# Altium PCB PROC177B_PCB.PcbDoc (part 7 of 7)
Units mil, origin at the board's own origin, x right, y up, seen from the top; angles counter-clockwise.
Board outline 4257.98 x 1561.15 mil, 4 copper layers (Top Layer, Int1 (GND), Int2 (PWR), Bottom Layer), stack 63.572 mil thick; 461 components, 307 nets, 1564 pads, 607 vias.
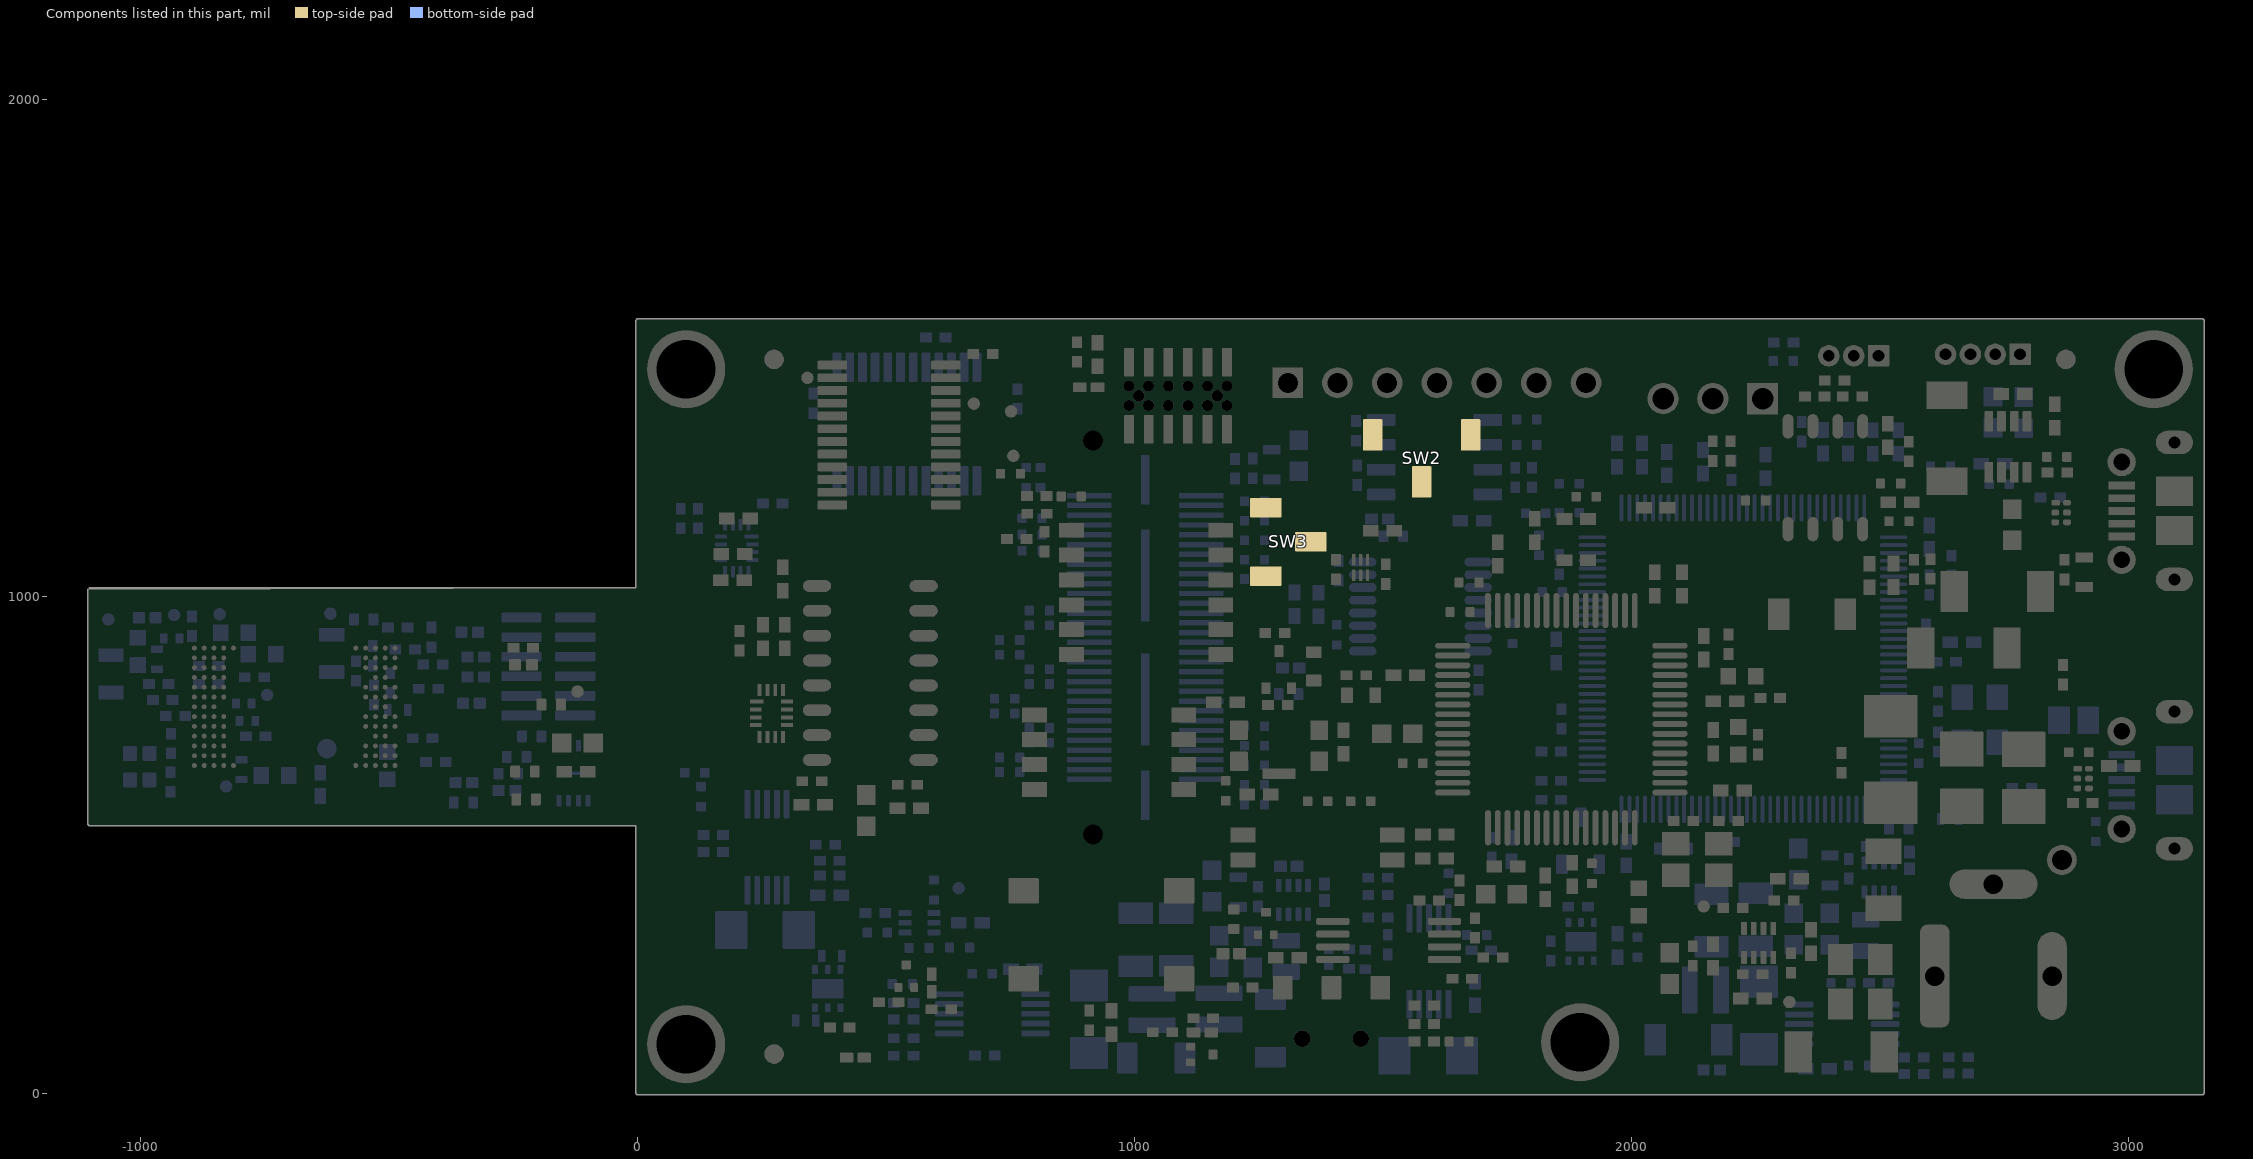
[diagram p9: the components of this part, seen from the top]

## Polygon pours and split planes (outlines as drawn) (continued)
VCC_SNSR_BRD on Bottom Layer "NONET_L08_P-001" (solid, remove dead copper, pour order 273): 1040,1542 980,1542 977,1539 977,1517 987,1507 1032,1507 1040,1515
VCC_SNSR_BRD on Bottom Layer "NONET_L08_P-001" (solid, remove dead copper, pour order 272): 1628.18,1272 1600,1272 1591,1263 1591,1233 1600,1224 1616,1224 1628.18,1236.18
VCC_3V3 on Bottom Layer "NONET_L08_P-001" (solid, remove dead copper, pour order 264): 17 vertices, not listed, extent 1636.25,1139.72 1780.1,1230.79
5V_IN on Bottom Layer "NONET_L08_P-001" (solid, remove dead copper, pour order 177): 18 vertices, not listed, extent 1111.91,403.48 1316.27,485.41
RADAR_1V8 on Bottom Layer "NONET_L08_P-001" (solid, remove dead copper, pour order 2): 25 vertices, not listed, extent -905.85,787.63 -810.81,976.73
RADAR_3V3 on Bottom Layer "NONET_L08_P-001" (solid, remove dead copper, pour order 26): 42 vertices, not listed, extent -477.29,613.27 -274.01,939.31
RADAR_1V8 on Bottom Layer "NONET_L08_P-001" (solid, remove dead copper, pour order 94): 27 vertices, not listed, extent -458.71,852.89 -404.39,907.91
5V_IN on Bottom Layer "NONET_L08_P-001" (solid, remove dead copper, pour order 161): 31 vertices, not listed, extent 2049,299.42 2494.08,518.33
REG_OUT_1V8 on Bottom Layer "NONET_L08_P-001" (solid, remove dead copper, pour order 171): 17 vertices, not listed, extent 2088.1,157.66 2528.67,330.96
RADAR_1V8 on Bottom Layer "NONET_L08_P-001" (solid, remove dead copper, pour order 174): 2295.93,123.74 2219.15,123.74 2217.51,122.55 2217.51,36.2 2225.44,28.27 2266.42,28.27 2295.93,57.79
VCC_3V3 on Bottom Layer "NONET_L08_P-001" (solid, remove dead copper, pour order 185): 837.7,193.38 842.24,197.92 842.24,250.87 831.61,261.5 783.66,261.5 783.66,226.96 772.06,215.36 772.06,194.95 773.63,193.38
5V_IN on Bottom Layer "NONET_L08_P-001" (solid, remove dead copper, pour order 198): 2760.39,1506.29 2760.39,1447.21 2770.37,1437.24 2770.37,1371.01 2807.77,1371.01 2807.77,1410.38 2803.7,1414.45 2803.7,1506.29 2801.75,1508.24 2762.34,1508.24
GND on Bottom Layer "NONET_L08_P-001" (solid, remove dead copper, pour order 226): 40 vertices, not listed, extent 2126.02,343.05 2569.34,460.64
VCC_XDS_3V3 on Bottom Layer "NONET_L-01_P-001" (solid, remove dead copper, pour order 247): 25 vertices, not listed, extent 1783.24,713.01 1952.19,884.16
VCC_XDS_3V3 on Bottom Layer "NONET_L-01_P-001" (solid, remove dead copper, pour order 248): 38 vertices, not listed, extent 2053.49,1089.14 2321.7,1288.64
VCC_XDS_3V3 on Bottom Layer "NONET_L-01_P-001" (solid, remove dead copper, pour order 249): 46 vertices, not listed, extent 2436.7,717.68 2753,1060.14
CONN_5V on Bottom Layer "NONET_L08_P-001" (solid, remove dead copper, pour order 202): 18 vertices, not listed, extent 1090,1177.06 1379,1271.99
5V_IN on Bottom Layer "NONET_L08_P-001" (solid, remove dead copper, pour order 206): 1311.95,1339.21 1320.7,1347.96 1365.57,1347.96 1375.12,1338.41 1375.12,1302.59 1366.82,1294.29 1311.95,1294.29
RADAR_3V3 on Bottom Layer "NONET_L08_P-001" (solid, remove dead copper, pour order 192): 45 vertices, not listed, extent -257.13,259.33 222.37,637.61
RADAR_1V2 on Bottom Layer "NONET_L08_P-001" (solid, remove dead copper, pour order 57): 46 vertices, not listed, extent -639.7,806 120.73,999.8
RADAR_1P2_RF on Bottom Layer "  " (solid, remove dead copper, pour order 95): 27 vertices, not listed, extent -1088.05,813.27 -899.7,966.28
RADAR_1V_RF_OUT on Bottom Layer "NONET_L08_P-001" (solid, remove dead copper, pour order 8): -801.35,698.05 -780.94,677.64 -780.94,660.92 -804.64,660.92 -804.64,672.1 -809.73,677.19 -823.04,677.19 -827.91,682.06 -827.91,692.49 -822.34,698.05
SW3 on Bottom Layer "NONET_L08_P-001" (solid, remove dead copper, pour order 221): 19 vertices, not listed, extent 2434.97,333.78 2499.53,417.95
SW2 on Bottom Layer "NONET_L08_P-001" (solid, remove dead copper, pour order 180): 22 vertices, not listed, extent 1277.92,291.2 1333.17,373.76
GND on Bottom Layer "NONET_L08_P-001" (solid, remove dead copper, pour order 179): 27 vertices, not listed, extent 958.8,296.38 1392.83,404.94
REG_OUT_1V2 on Bottom Layer "NONET_L08_P-001" (solid, remove dead copper, pour order 181): 19 vertices, not listed, extent 970.29,184.22 1443.41,277.5
VCC_XDS_3V3 on Bottom Layer "NONET_L-01_P-001" (solid, remove dead copper, pour order 262): 21 vertices, not listed, extent 1821.14,1017.45 1950.43,1061.5
RADAR_1P2_RF on Bottom Layer "NONET_L08_P-001" (solid, remove dead copper, pour order 188): 1622.85,113.52 1622.85,43.46 1622.37,42.99 1627.83,37.53 1700.51,37.53 1738.48,75.5 1738.48,118.06 1727.22,129.32 1698.48,129.32 1682.68,113.52
REG_1V2 on Bottom Layer "NONET_L08_P-001" (solid, remove dead copper, pour order 182): 867.12,50.25 895.95,21.41 940.64,21.41 1014.16,21.19 1014.16,99.91 1032.91,118.66 1082.64,118.66 1086.01,122.03 1086.01,148.02 1081.31,152.72 963.04,152.72 941.95,131.64 868.13,131.64 867.73,132.04 867.12,131.43
RADAR_3V3 on Bottom Layer "NONET_L08_P-001" (solid, remove dead copper, pour order 105): -439.41,724.22 -505.88,724.22 -522.98,707.12 -522.98,676.26 -517.63,670.91 -486.76,670.91 -475.58,682.09 -467.56,682.09 -463.18,686.46 -463.18,698.13 -457.59,703.72 -439.61,703.72
VCC_LVDS_3V3 on Bottom Layer "NONET_L08_P-001" (solid, remove dead copper, pour order 213): 599.76,682.34 606.38,675.72 609,673.1 609,651.6 591.91,634.52 508.28,634.52 502.84,639.96 502.84,677.38 507.8,682.34
CONN_5V on Bottom Layer "NONET_L08_P-001" (solid, remove dead copper, pour order 203): 964.1,1196.74 970.12,1190.72 998.95,1190.72 1004.5,1195.93 1004.5,1227.53 998.21,1233.82 875.22,1233.82 865,1223.6 864.73,1196.74
GND on Bottom Layer "NONET_L08_P-001" (solid, remove dead copper, pour order 195): 21 vertices, not listed, extent 1827.85,285.23 1983.74,389.4
5V_IN on Bottom Layer "NONET_L08_P-001" (solid, remove dead copper, pour order 194): 1814,299.58 1811.37,302.21 1791.7,302.21 1786,296.51 1786,286.8 1786,258.86 1793.76,251.1 1870.6,251.1 1877.17,257.67 1878.24,257.67 1879.12,258.55 1879.12,274.25 1875.19,278.17 1824.38,278.17 1814,288.56
5V_IN on Bottom Layer "NONET_L08_P-001" (solid, remove dead copper, pour order 208): 20 vertices, not listed, extent 350.69,119.48 476.15,197.6
GND on Bottom Layer "NONET_L08_P-001" (solid, remove dead copper, pour order 193): 23 vertices, not listed, extent 295.67,113.54 448,291.6
VCC_3V3 on Bottom Layer "NONET_L08_P-001" (solid, remove dead copper, pour order 190): 22 vertices, not listed, extent 292.86,240.03 386.07,437.12
REG_RF_1V2 on Bottom Layer "NONET_L08_P-001" (solid, remove dead copper, pour order 183): 20 vertices, not listed, extent 1123.18,21.97 1558.27,154.1
GND on Bottom Layer "NONET_L08_P-001" (solid, remove dead copper, pour order 187): 1242.5,208.84 1242.5,168.94 1267.2,144.24 1341.83,144.24 1357.16,159.57 1357.16,193.44 1341.26,209.34 1243.01,209.34
GND on Bottom Layer "NONET_L08_P-001" (solid, remove dead copper, pour order 204): 1192.93,1264.23 1247.87,1264.23 1268.16,1284.52 1294.27,1284.52 1294.27,1311.87 1273.38,1332.76 1215.43,1332.76 1192.98,1310.32
RADAR_SRAM_1V2 on Bottom Layer "NONET_L08_P-001" (solid, remove dead copper, pour order 56): -541.41,962.33 -539.43,964.31 -489.05,964.31 -482.85,958.07 -482.85,903.61 -481.88,902.64 -473.42,902.64 -473.42,882.66 -481.86,874.22 -509.12,874.22 -513.89,878.99 -513.89,938.88 -517.26,942.25 -538.69,942.25 -541.41,944.98
VBUS_1_DETECT on Bottom Layer "NONET_L08_P-001" (solid, remove dead copper, pour order 207): 1944.87,634.29 1882.52,634.29 1874.43,642.38 1850.81,642.38 1846.87,638.44 1846.87,580.76 1870.49,580.76 1870.49,600.44 1884.65,614.6 1942.5,614.6 1948.81,620.91 1948.81,632.49 1947,634.3
LIN_VDD on Bottom Layer "NONET_L08_P-001" (solid, remove dead copper, pour order 201): 2679.48,1349.09 2679.48,1331.72 2693.18,1318.02 2807.77,1318.02 2807.77,1358.15 2688.54,1358.15
VBAT on Bottom Layer "NONET_L08_P-001" (solid, remove dead copper, pour order 200): 2708.68,1500.68 2708.68,1475.28 2717.81,1466.15 2717.81,1420.05 2708.89,1411.14 2708.89,1371.77 2746.3,1371.77 2746.3,1470.11 2754.18,1477.99 2754.18,1498.01 2742.05,1510.14 2724.86,1510.14
VCC_3V3 on Bottom Layer "NONET_L08_P-001" (solid, remove dead copper, pour order 189): 1714.77,196.84 1727,184.6 1727,165.6 1712.79,151.4 1626.91,151.4 1625.53,151.97 1624.96,152.54 1624.96,207.34 1626.11,208.48 1635.63,208.48 1636.77,207.34 1636.77,206.53 1646.47,196.84
GND on Bottom Layer "NONET_L08_P-001" (solid, remove dead copper, pour order 186): 1139.65,106.27 1149.17,96.76 1149.17,47.52 1137.06,35.41 1057.69,35.41 1052.57,40.52 1052.57,98.69 1060.16,106.27
RADAR_1V2 on Bottom Layer "NONET_L08_P-001" (solid, remove dead copper, pour order 184): 862.29,272.12 862.29,288.89 874,300.6 935,300.6 949.02,286.58 949.02,165.6 868.04,165.6 861.61,172.04 861.7,172.13 861.7,271.53
GND on Bottom Layer "NONET_L08_P-001" (solid, remove dead copper, pour order 176): 2026.14,138.95 2098.65,138.95 2104,133.6 2104,81.84 2092.21,70.05 2032.04,70.05 2026.14,75.96
VCC_3V3 on Bottom Layer "NONET_L08_P-001" (solid, remove dead copper, pour order 175): 2308.75,57.07 2291.19,39.51 2283.17,31.49 2283.17,20.8 2289.09,14.88 2289.28,15.07 2312.92,15.07 2356.49,15.07 2371,29.59 2371,101.17 2371.31,101.48 2367.2,105.58 2310.95,105.58 2308.75,103.37
REG_1V8 on Bottom Layer "NONET_L08_P-001" (solid, remove dead copper, pour order 173): 2296.86,182.15 2235.1,182.15 2203.96,151.01 2203.96,78.23 2196.99,71.26 2160.21,71.26 2152.65,78.82 2152.65,148.17 2164.38,159.91 2164.38,252.78 2173.45,261.85 2289.61,261.85 2296.86,254.59
GND on Bottom Layer "NONET_L08_P-001" (solid, remove dead copper, pour order 103): -528.45,936.11 -522.06,929.72 -522.06,888.13 -541.74,888.13 -551.64,898.03 -556.38,898.03 -574.56,916.21 -574.56,928.42 -566.87,936.11
GND on Bottom Layer "NONET_L08_P-001" (solid, remove dead copper, pour order 25): -84.38,713.31 -78.02,706.94 -78.02,655.09 -93.13,639.98 -158.49,639.98 -159.66,641.14 -159.66,650.66 -156.03,654.29 -119.32,654.29 -104.12,669.48 -104.12,710.55 -101.36,713.31
RADAR_1V_RF_OUT on Bottom Layer "NONET_L08_P-001" (solid, remove dead copper, pour order 107): 19 vertices, not listed, extent -823.54,826.28 -766.31,901.26
RADAR_1V4_APLL on Bottom Layer "NONET_L08_P-001" (solid, remove dead copper, pour order 11): -796.96,774.77 -804.54,767.19 -823.82,767.19 -827.95,762.89 -838.81,762.89 -841.42,765.5 -841.42,774.91 -831.38,784.95 -826.83,784.95 -813.98,797.8 -800.21,797.8 -796.96,794.55
RADAR_3V3 on Bottom Layer "NONET_L08_P-001" (solid, remove dead copper, pour order 42): -265.85,775.7 -271.26,770.28 -278.8,770.28 -278.8,722.93 -259.72,703.85 -219.2,703.85 -215.2,707.85 -215.2,730.47 -200.83,744.84 -187.4,744.84 -184.1,748.14 -184.57,748.61 -184.57,771.46 -188.11,774.99
RADAR_1V4_SYNTH on Bottom Layer "NONET_L08_P-001" (solid, remove dead copper, pour order 12): -792.57,758.77 -822.37,758.77 -827.03,754.1 -827.03,742.69 -822.71,738.37 -792.29,738.37 -790.2,740.46 -790.2,755.71
RADAR_1V8 on Bottom Layer "NONET_L08_P-001" (solid, remove dead copper, pour order 7): -922.93,771.24 -873.18,771.24 -871.82,769.88 -868.73,766.79 -868.73,750.61 -875.34,744 -920.63,744 -924.99,748.36 -924.99,769.18
RADAR_VBGAP on Bottom Layer "NONET_L08_P-001" (solid, remove dead copper, pour order 6): -891.37,799.43 -891.37,784.57 -894.97,780.97 -946.15,780.97 -946.66,781.48 -946.66,800.98 -945.96,801.68 -893.62,801.68
GND on Int2 (PWR) "NONET_L08_P-001" (solid, remove dead copper, pour order 261): 12.56,1542.25 3136.17,1542.25 3136.17,12.61 12.56,12.61
GND on Int2 (PWR) "NONET_L08_P-001" (solid, remove dead copper, pour order 212): -1089.6,1001.51 0.02,1001.51 0.02,541.26 -1089.6,541.26
RADAR_1P2_RF on Int2 (PWR) "RADAR_1P2_RF_L03_P148" (solid, remove dead copper, pour order 148): 49 vertices, not listed, extent -1089.13,52.72 1739.1,1001.09
GND on Int2 (PWR) "NONET_L08_P-001" (solid, remove dead copper, pour order 216): 802.38,1028.27 757.04,1073.6 308.73,1073.6 308.73,629.5 411.2,527.03 753.43,527.03 802.38,575.98
5V_IN on Int2 (PWR) "NONET_L08_P-001" (solid, remove dead copper, pour order 232): 39 vertices, not listed, extent 439.76,156.18 2118.02,481.06
RADAR_1V8 on Int2 (PWR) "NONET_L08_P-001" (solid, remove dead copper, pour order 209): 18 vertices, not listed, extent -890.33,871.64 127.75,996.77
RADAR_1V8 on Int2 (PWR) "Int2 (PWR)-RADAR_1V8" (solid, remove dead copper, pour order 205): 44 vertices, not listed, extent 70.42,4.64 2288,390.02
RADAR_1V2 on Int2 (PWR) "NONET_L-01_P-001" (solid, remove dead copper, pour order 152): 17 vertices, not listed, extent 138.86,255.71 926.72,632.03
RADAR_1V8 on Int2 (PWR) "NONET_L08_P-001" (solid, remove dead copper, pour order 246): 106.3,923 98.54,915.24 98.54,883.89 98.42,883.77 105.42,876.77 117.42,876.77 125.42,884.77 125.42,916.77 119.42,922.77
GND on Int1 (GND) "Int1 (GND)-GND" (solid, remove dead copper, pour order 265): 12.42,13.72 3136.49,13.72 3136.49,1542.71 12.42,1542.71 12.42,1006.87 -1094.56,1006.87 -1094.56,553.75 12.42,553.75

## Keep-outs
Top Layer:
  region: -472.42,541.26 -472.42,1013.78 -275.57,1013.78 -275.57,541.26
  region: -905.49,1013.78 -905.49,541.26 -1102.34,541.26 -1102.34,1013.78
Keep-Out Layer:
  circle w4: c3051.18,1456.69 r118.11
  circle w4: c1896.85,102.75 r118.11
  circle w1: c917.09,1313.06 r30
  circle w1: c917.09,520.54 r30
  circle w6: c98.41,1456.71 r118.11
  circle w6: c98.43,98.43 r118.11
  text ".Layer_Name" at -304.89,-905.63 h60

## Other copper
Top Layer:
  text ".Layer_Name" at -554.89,-905.63 h60
Int1 (GND):
  text ".Layer_Name" at -537,-906 h60
Int2 (PWR):
  text ".Layer_Name" at -537,-906 h60
Bottom Layer:
  pour cut-out: -964.32,745.39 -894.72,745.39 -870.69,721.35 -870.69,616.21 -905.29,581.6 -1047.34,581.6 -1066.93,601.2 -1066.93,707.17 -1041.55,732.56 -976.54,732.56
  text ".Layer_Name" at -554.89,-905.63 h60

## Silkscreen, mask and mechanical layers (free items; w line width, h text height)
Top Overlay:
  drawing of 205 lines, arcs and shapes, not listed
  text "GND" at 1166.86,1512.5 h25
  text "3V3" at 957,1512 h25
  text "HOST_CLK" at 447.09,1498.93 h25
  text "CAN" at 2579.27,1478.04 h23 r90
  text "LIN" at 2661.08,1440.84 h20
  text "NERROR" at 803.39,1374.87 h22
  text "WU_REQIN" at 198.41,1367.83 h20
  text "SPI_HEADER" at 1256.42,1364.95 h25
  text "RTC_CLK" at 699.28,1336.88 h23
  text "SDA" at 2113.42,1335.47 h25
  text "SCL" at 2225.05,1332.57 h25
  text "GND" at 2023.47,1329.12 h25
  text "5V" at 1356.52,1312.91 h25
  text "3V3" at 1753.89,1308.42 h25
  text "P_CLKO" at 742.62,1298.13 h22
  text "I2C" at 2025.24,1280.35 h25
  text "I/F CONN" at 1106.5,1263.9 h25
  text "SOP1" at 1101.69,1207 h26
  text "JTAG" at 685.26,1055.05 h26
  text "LVDS" at 732.77,1015.03 h26
  text "XDS_USB" at 2973.88,972 h22
  text "TEXAS" at -404.33,967.76 h20
  text "RS232" at 711.33,967.76 h26
  text "INSTRUMENTS" at -458.14,928.97 h20
  text "FOR DEMO" at 2898.69,924.89 h30
  text "CAN/UARTA" at 615.09,920.17 h26
  text "PGOOD" at 1402.3,906.14 h24
  text "I2C/SPI" at 675.76,870.48 h26
  text "FTDI" at 1521.52,789.29 h20
  text "SOP1" at -134.37,765.65 h25
  text "USER_SW" at 1340.35,763.77 h20
  text "CAN_EN" at 623.4,754.63 h25
  text "LIN_EN" at 627.41,707.14 h25
  text "FTDI_DCA" at 609.79,663.15 h21
  text "_SPI" at 643.97,628.96 h21
  text "R" at -918.61,627.51 h4.54
  text "R" at -918.61,627.51 h4.54
  text "PROC177 REV. B" at 166,613 h40 r90
  text "PROC177 REV. B" at -819.21,576.62 h40
  text "MISTRAL" at -1073.25,562.27 h41.62
  text "R" at 802.67,525.72 h4.54
  text "R" at 802.67,525.72 h4.54
  text "XDS_I2C_SW" at 993.66,496.14 h20
  text "GND" at 2755.89,470.97 h25
  text "MISTRAL" at 648.03,460.47 h41.62
  text "SL#" at 83.19,305.04 h40
  text "RESET_SW" at 703.13,124.62 h25
  text "U_LED" at 1240.28,87.52 h20 r90
  text "5V" at 361.92,63.1 h20
  text "RESET_LED" at 689.15,56.7 h25 r90
  text "5V_PWR" at 3004.44,25.27 h22
  text "FUNCTIONAL MODE" at 892.47,23.88 h23
  text "FLASHING MODE" at 1546.83,11.32 h23
  text ".Layer_Name" at -304.89,-905.63 h60
Bottom Overlay:
  circle w15: c1445.29,1191.56 r2.66
  circle w15: c1350.5,156.17 r3.1
  circle w15: c1739.06,1076.55 r3.1
  circle w15: c1850.21,363.54 r0.51
  lines w4: -919.68,961.79 -919.68,967.22 -914.3,972.6 ; 474.1,183.6 480.54,177.17 497.41,177.17 ; 711.93,842.64 720.2,834.38 772.25,834.38 ; 726,963.6 730.78,958.82 737.76,958.82 772.37,958.82 ; 776,929.6 776,979.6 ; 776.21,815.6 776.3,815.52 776.3,851.99 ; 816.01,674.15 816.01,634.88 827,623.89 ; 944,25.6 956,37.6 956,38.6 956,124.13 970.48,138.61 970.48,159.13 ; 1055,428.6 1105.51,428.6 1122.77,411.34 1122.77,376.43 1122.77,351.64 1123.37,351.05 1123.37,350.63 1128.94,345.05 1198.01,345.05 1198.51,344.55 ; 2240,492.6 2240,515.96 2260.84,536.8 2419.3,536.8 2435.27,520.83 2435.27,487.65 ; 2418.87,253.22 2455.49,253.22 2459,249.72 ; 2578,649.6 2578,639.58 2588.97,628.6
  text "VBAT" at 2766.41,1514.38 h20
  text "GND" at 2473.1,1509.24 h23
  text "CANL" at 2526.75,1462.26 h23 r270
  text "CANH" at 2348.88,1455.52 h23 r270
  text "I2C_HEADER" at 2209.65,1447.1 h25
  text "5V_IN" at 2827.4,1438.49 h20
  text "GND" at 2618.55,1391.51 h23 r270
  text "DCA1000_CONN" at 1168.87,1348.49 h25
  text "LIN_BUS" at 2661.77,1307.91 h23 r270
  text "I/F CONN" at -104.24,981.36 h20
  text "GPADC1" at -844.4,978.54 h20
  text "1V2" at -622.29,978.09 h20
  text "GND" at -278.75,965.26 h20
  text "1V8" at -770.19,951.07 h20
  text "1P2RF" at -1047.71,898.98 h20 r270
  text "TEXAS" at 2935.21,891.52 h25
  text "INSTRUMENTS" at 2996.07,856.02 h25
  text "GND" at -752.15,732.38 h20 r270
  text "3V3" at -260.49,722.9 h20
  text "VPP" at -642.78,716.8 h25 r270
  text "FY23-24/01286000102" at 276.04,645.94 h25 r270
  text "OSC_CLKOUT" at -713.26,571.59 h22
  text "3V3" at 731.41,434.71 h25
  text "FTDI_USB" at 3115.28,423.93 h25
  text "FOR RAW ADC" at 3120.15,373.06 h25
  text ".Layer_Name" at -304.89,-905.63 h60
Top Paste:
  region: -781.45,721.97 -719.54,721.97 -719.54,672.03 -781.45,672.03
  region: -712.73,721.97 -650.82,721.97 -650.82,672.03 -712.73,672.03
  region: -712.73,897.71 -650.82,897.71 -650.82,847.78 -712.73,847.78
  region: -712.73,839.31 -650.82,839.31 -650.82,789.38 -712.73,789.38
  region: -712.73,780.55 -650.82,780.55 -650.82,730.62 -712.73,730.62
  region: -781.45,780.55 -719.54,780.55 -719.54,730.62 -781.45,730.62
  region: -781.45,839.31 -719.54,839.31 -719.54,789.38 -781.45,789.38
  region: -781.45,897.71 -719.54,897.71 -719.54,847.78 -781.45,847.78
  text ".Layer_Name" at -304.89,-905.63 h60
Bottom Paste:
  text ".Layer_Name" at -304.89,-905.63 h60
Top Solder:
  region: -712.73,897.71 -650.82,897.71 -650.82,847.78 -712.73,847.78
  region: -712.73,839.31 -650.82,839.31 -650.82,789.38 -712.73,789.38
  region: -712.73,780.55 -650.82,780.55 -650.82,730.62 -712.73,730.62
  region: -712.73,721.97 -650.82,721.97 -650.82,672.03 -712.73,672.03
  region: -781.45,721.97 -719.54,721.97 -719.54,672.03 -781.45,672.03
  region: -781.45,780.55 -719.54,780.55 -719.54,730.62 -781.45,730.62
  region: -781.45,839.31 -719.54,839.31 -719.54,789.38 -781.45,789.38
  region: -781.45,897.71 -719.54,897.71 -719.54,847.78 -781.45,847.78
  text ".Layer_Name" at -304.89,-905.63 h60
  text ".Layer_Name" at -304.89,-905.63 h60
Bottom Solder:
  region: -724.57,857.15 -651.21,857.15 -651.21,696.47 -724.57,696.47
  lines w20: -1090.48,553.27 -1009.45,553.27 ; -1090.34,555.79 -1090.34,601.79 ; -1090.35,703.54 -1090.35,753.54 ; -1089.36,980.6 -1089.36,1002.6 -1029.36,1002.61 ; -906.45,553.27 -756.45,553.27 ; -656.45,553.27 -506.45,553.27 ; -56.95,659.44 -56.95,689.44
  text ".Layer_Name" at -304.89,-905.63 h60
Drill Guide:
  text ".Layer_Name" at -304.89,-905.63 h60
M1 Board Outline:
  lines w6: -1102.34,541.26 0.02,541.26 ; -1102.34,541.34 -1102.34,1013.78 0.02,1013.78 ; -1102.34,560.94 -1102.34,994.1 ; -1082.65,541.26 0.02,541.26 ; -1082.65,1013.78 0.02,1013.78 ; 222.1,0 0,0 ; 222.12,1555.12 0,1555.12 ; 371.71,0 2847.22,0 ; 371.73,1555.12 2847.2,1555.12 ; 2996.82,0 3149.61,0 ; 0,0 0.02,541.26 ; 0,0 3149.61,0 ; 0,0 0.02,541.26 ; 0.02,1013.78 0.01,1555.12 ; 0.02,1013.78 0,1555.12 ; 0,1555.12 0.02,1555.12 ; 0,1555.12 3149.61,1555.12 ; 3149.61,0 3149.61,1555.12 ; 3149.61,0 3149.61,1555.12 ; 3149.61,1555.12 3149.61,1555.12 ; -36.37,625.39 ccw(c-11.37,625.39) -11.37,600.39 11.4,600.39 ccw(c11.4,625.39) 36.4,625.39 36.4,650.05 ccw(c11.4,650.05) 11.4,675.05 -11.36,675.05 ccw(c-11.37,650.05) -36.37,650.05 -36.37,625.39 ; -36.36,905.07 ccw(c-11.36,905.07) -11.36,880.07 11.4,880.07 ccw(c11.4,905.07) 36.4,905.07 36.4,929.72 ccw(c11.4,929.72) 11.4,954.72 -11.36,954.72 ccw(c-11.36,929.72) -36.36,929.72 -36.36,905.07 ; -36.36,914.98 -36.36,914.98 ; -36.36,620.42 -34.93,615.69 -32.58,611.27 -29.41,607.39 -25.55,604.21 -21.13,601.85 -16.34,600.39 -12.02,600.37 9.49,599.68 11.16,599.64 16.2,600.18 21.03,601.68 25.49,604.09 29.39,607.31 32.6,611.23 36.4,620.42 36.41,655.02 34.98,659.74 32.63,664.17 29.46,668.04 25.59,671.23 21.17,673.59 16.38,675.05 -16.34,675.05 -21.06,673.62 -25.49,671.26 -29.37,668.08 -32.56,664.21 -36.36,655.02 -36.36,620.42 ; -36.36,760.26 -34.93,755.54 -32.58,751.11 -29.41,747.23 -25.54,744.05 -21.12,741.69 -16.33,740.23 -13.98,740.23 13.62,740.81 16.6,741.11 21.31,742.38 25.66,744.57 29.5,747.59 32.64,751.31 34.98,755.6 36.41,760.26 36.41,794.86 34.98,799.6 32.62,804.02 29.45,807.89 25.59,811.07 21.17,813.43 16.38,814.88 -16.33,814.88 -21.07,813.45 -25.49,811.1 -29.36,807.93 -32.54,804.06 -34.91,799.65 -36.36,794.86 -36.36,760.26 ; -36.36,765.23 ccw(c-11.36,765.23) -11.36,740.23 11.41,740.23 ccw(c11.41,765.23) 36.41,765.23 36.41,789.89 ccw(c11.41,789.89) 11.41,814.89 -11.36,814.89 ccw(c-11.36,789.89) -36.36,789.89 -36.36,765.23 ; -36.36,900.1 -36.36,934.69 -34.91,939.48 -32.54,943.9 -29.36,947.76 -25.49,950.94 -21.07,953.29 -16.33,954.72 16.38,954.72 25.57,950.92 29.44,947.73 32.62,943.85 34.97,939.43 36.41,934.69 36.41,900.1 34.96,895.31 32.59,890.89 29.41,887.03 25.54,883.85 21.12,881.5 16.38,880.07 -16.33,880.07 -25.52,883.87 -29.39,887.06 -32.57,890.94 -34.92,895.36 -36.36,900.1
M2 Board Dimensions:
  text ".Layer_Name" at -566.77,-903.68 h60
M3 3D STEP Top:
  text ".Layer_Name" at -304.89,-905.63 h60
M4 3D STEP Bottom:
  text ".Layer_Name" at -304.89,-905.63 h60
M5 Assembly Top:
  lines w1: 1662.26,555.72 1662.26,555.87
  lines w2.67: 69.62,433.23 ccw(c82.97,433.23) 82.97,419.88 403.47,419.88 ccw(c403.47,433.23) 416.83,433.23 416.83,513.36 ccw(c403.47,513.36) 403.47,526.71 82.97,526.71 ccw(c82.97,513.36) 69.62,513.36 69.62,433.23
  lines w10: -1173.89,-977.3 5426.11,-977.3 ; -1173.89,-773.97 5428.11,-773.97 ; -1173.89,-570.63 -1173.89,-1180.63 2831.11,-1180.63 5428.11,-1180.63 5428.11,-570.63 -1173.39,-570.63 -1173.39,-1180.63 402.11,-1180.63 ; 1291.11,-1180.63 1291.11,-570.63 ; 2558.11,-773.97 2558.11,-570.63 ; 3398.11,-773.97 3398.11,-570.63 ; 4020.11,-1187.13 4020.11,-984.3
  text "COMPONENTS MARKED 'DNP' SHOULD NOT BE POPULATED." at -95.68,3736.39 h60
  text "ASSEMBLY VARIANT:" at -96.18,3620.89 h60
  text ".VariantName" at 939.82,3620.89 h60
  text ".Designator" at 211.17,462.61 h21.37
  text "PCB VIEWED FROM TOP SIDE" at -1099.62,-700.81 h60
  text "BOARD #:" at 1376.88,-700.81 h60
  text ".PRJ_Number" at 1922.38,-700.81 h60
  text "REV:" at 2766.88,-700.81 h60
  text ".PCB_Rev" at 3058.38,-700.81 h60
  text "SVN REV:" at 3604.88,-700.81 h60
  text ".VersionControl_RevNumber" at 4110.88,-700.81 h60
  text "Assembly Layer Top" at -304.12,-900.15 h60
  text "TID #:" at 1376.88,-904.15 h60
  text ".TID" at 1922.38,-904.15 h60
  text "PLOT NAME =" at -1099.62,-1109.48 h60
  text ".plot_File_Name" at -294.12,-1109.48 h60
  text "GENERATED    :" at 1378.88,-1109.48 h60
  text ".Print_Date" at 2248.38,-1109.48 h60
  text ".Print_Time" at 2977.38,-1109.48 h60
  text "TEXAS INSTRUMENTS" at 4241.88,-1109.48 h60
M6 Assembly Bottom:
  lines w10: -1174.39,-774.47 5427.61,-774.47 ; -1172.39,-977.8 5427.61,-977.8 ; 233.61,-1187.63 233.61,-984.8 ; 855.61,-774.47 855.61,-571.13 ; 1695.61,-774.47 1695.61,-571.13 ; 2962.61,-1181.13 2962.61,-571.13 ; 3851.61,-1181.13 5427.11,-1181.13 5427.11,-571.13 -1174.39,-571.13 -1174.39,-1181.13 1422.61,-1181.13 5427.61,-1181.13 5427.61,-571.13
  text "COMPONENTS MARKED 'DNP' SHOULD NOT BE POPULATED." at 6085,-371.4 h60
  text ".VariantName" at 4380.69,-464.09 h60
  text "ASSEMBLY VARIANT:" at 5419.69,-464.09 h60
  text ".VersionControl_RevNumber" at 153.61,-703.3 h60
  text "SVN REV:" at 659.61,-703.3 h60
  text ".PCB_Rev" at 1206.11,-703.3 h60
  text "REV:" at 1497.61,-703.3 h60
  text ".PRJ_Number" at 2342.11,-703.3 h60
  text "BOARD #:" at 2887.61,-703.3 h60
  text "PCB VIEWED FROM BOTTOM SIDE" at 5364.11,-703.3 h60
  text "Assembly Bottom Layer" at 5003.11,-892.13 h60
  text ".TID" at 2342.11,-906.63 h60
  text "TID #:" at 2887.61,-906.63 h60
  text "TEXAS INSTRUMENTS" at 22.61,-1111.97 h60
  text ".Print_Time" at 1287.11,-1111.97 h60
  text ".Print_Date" at 2016.11,-1111.97 h60
  text "GENERATED    :" at 2885.61,-1111.97 h60
  text ".plot_File_Name" at 4558.61,-1111.97 h60
  text "PLOT NAME =" at 5364.11,-1111.97 h60
M10 Fab Notes:
  drawing of 255 lines, arcs and shapes, not listed
  text "1" at -392.05,7989.37 h70
  text "2" at 2103.61,7989.37 h70
  text "3" at 4592.95,7989.37 h70
  text "4" at 7099.62,7989.37 h70
  text "5" at 9598.61,7989.37 h70
  text "6" at 12103.61,7989.37 h70
  text "A" at -1548.39,6846.37 h70
  text "A" at 13251.61,6846.37 h70
  text "DESIGN INFORMATION" at 11250.13,6309.04 h60
  text "4" at 11644.61,6179.65 h60
  text "MIN. TRACK WIDTH:" at 10605.57,6176.91 h60
  text "MIL" at 11856.57,6176.91 h60
  text "4" at 11642.07,6060.26 h60
  text "MIN. CLEARANCE:" at 10605.57,6052.79 h60
  text "MIL" at 11856.57,6052.79 h60
  text "MIN. VIA PAD SIZE:" at 10605.57,5928.66 h60
  text "18" at 11628.26,5921.29 h60
  text "MIL" at 11879.11,5919.87 h60
  text "EXTERNAL" at 12126.71,5801.36 h60
  text "0.127mm (5.0MIL)" at 11300.57,5798.76 h60
  text "MINIMUM ANNULAR RING" at 10276.34,5790.54 h60
  text "PER" at 10476.34,5680.41 h60
  text "IPC-D-275 CLASS 2 LEVEL C" at 10696.34,5680.41 h60
  text "MIL, HOLES" at 12184.57,5579.93 h60
  text "+/-" at 11792.11,5571.35 h60
  text "+/-" at 12646.11,5571.35 h60
  text "REGISTRATION TOLERANCES:" at 10276.34,5570.28 h60
  text "METAL" at 11476.11,5570.28 h60
  text "5" at 12052.31,5570.29 h60
  text "3" at 12885.31,5570.29 h60
  text "MIL" at 13001.57,5570.28 h60
  text "HOLE SIZE TOLERANCE (UNLESS OTHERWISE SPECIFIED):" at 10276.34,5471.97 h60
  text "+/-" at 12646.11,5469.1 h60
  text "3" at 12885.31,5468.03 h60
  text "MIL" at 13001.57,5468.03 h60
  text "MATERIAL:" at 10201.57,5330.38 h60
  text "FR-4 High Tg" at 11188.01,5201.86 h60
  text "X" at 11930.11,5196.87 h60
  text "REFER STACK-UP" at 12430.96,5196.27 h55
  text "FR-408" at 10622.57,5189.35 h60
  text "OTHER" at 12110.57,5189.35 h60
  text "X" at 12101.12,5048.87 h60
  text "62 MIL (1.6mm) +/-10%" at 10942.67,5046.32 h60
  text "66 MIL +/-10%" at 12523.11,5039.87 h45
  text "THICKNESS:" at 10276.34,5038.1 h60
  text "OTHER" at 12227.57,5038.1 h60
  text "TOLERANCE:" at 10276.34,4899.79 h60
  text "X" at 11124.58,4899.79 h60
  text "ANSI IPC-6012 TYPE 3 CLASS 2" at 11302.59,4899.79 h60
  text "OTHER +/-" at 11302.57,4755.6 h60
  text "BOW & TWIST:" at 10276.34,4610.41 h60
  text "X" at 11124.58,4610.41 h60
  text "ANSI IPC-6012 TYPE 3 CLASS 2" at 11302.59,4610.41 h60
  text "B" at -1548.39,4466.37 h70
  text "B" at 13251.61,4466.37 h70
  text "OTHER +/-" at 11302.57,4463.71 h60
  text "DRILLING:" at 10201.57,4333.09 h60
  text "NC_DRILL FILES" at 11962.57,4227.91 h60
  text "REFERENCE:" at 10276.34,4223.97 h60
  text "X" at 10933.58,4223.87 h60
  text "AS SHOWN" at 11111.57,4223.97 h60
  text "X" at 11834.58,4223.97 h60
  text "OTHER" at 12260.57,4081.72 h60
  text "PTH COPPER THICKNESS:" at 10276.02,4078.19 h60
  text "X" at 11415.25,4078.19 h60
  text "20-30 um" at 11543.25,4078.19 h60
  text "BOARD FINISH:" at 10201.57,3930.59 h60
  text "SILKSCREEN:" at 10356.79,3820.46 h60
  text "X" at 11314.58,3820.46 h60
  text "TOP" at 11431.57,3820.46 h60
  text "X" at 11824.58,3820.46 h60
  text "BOTTOM" at 11942.57,3820.46 h60
  text "NOTES:" at 3640.45,3711.89 h60
  text "SILKSCREEN COLOR:" at 10356.79,3665.28 h60
  text "X" at 11313.58,3665.28 h60
  text "WHITE" at 11431.57,3665.28 h60
  text "OTHER" at 11942.57,3665.28 h60
  text "1. BOARD SHALL MEET THE REQUIREMENTS OF UL-796E WITH FLAMMABILITY RATING OF MINIMUM 94V-0. UL LOGO," at 3667.2,3566.06 h60
  text "GREEN" at 11562.57,3521.83 h60
  text "X" at 12036.58,3521.83 h60
  text "OTHER" at 12180.57,3521.83 h60
  text "RED" at 12553.11,3521.83 h60
  text "SOLDER RESIST COLOR:" at 10356.79,3514.96 h60
  text "MANUFACTURER'S IDENTIFICATION AND DATE CODE LETTER SHALL BE RENDERED IN SILKSCREEN." at 3773.93,3467.07 h60
  text "MATTE" at 11562.57,3367.58 h60
  text "SEMI-GLOSS" at 12180.11,3366.94 h60
  text "X" at 12036.18,3364.88 h60
  text "2. VENDOR MAY ADJUST SOLDERMASK WHEREVER SOLDERMASK PADS ARE THE SAME SIZE (1:1) AS PER THE MANUFACTURING CAPABILITIES" at 3660.21,3341.28 h60
  text "AND ALL OTHER SOLDER MASK PADS SHALL NOT BE MODIFIED, PROVIDED NO ADJACENT COPPER IS EXPOSED AND NO CONFLICT IS PRODUCED" at 3766.94,3242.29 h60
  text "IMMERSION GOLD (ENIG)" at 11262.57,3194.8 h60
  text "X" at 11086.42,3190.55 h60
  text "ENEPIG" at 12600.11,3187.58 h60
  text "SURFACE FINISH:" at 10201.57,3186.58 h60
  text "WITH ANY STATED \"VIA TENTING/COVERING\" REQUIREMENTS." at 3766.94,3149 h60
  text "IMM. TIN/SILVER OR EQUIV" at 10531.11,3049.27 h60
  text "OTHER" at 11962.57,3045.33 h60
  text "3. MANUFACTURER'S IDENTIFICATION,DATECODE LETTER SHALL BE SILKSCREENED ON SOLDER SIDE OF THE BOARD." at 3663.89,3030.9 h60
  text "4. TRACE WIDTH SHOULD BE ACCURATELY ETCHED. MAX TOLERANCE +/- 1 MIL." at 3658.93,2894.57 h60
  text "ARRAY/PANEL:" at 10201.57,2889.95 h60
  text "CUT AND TRIM PER M1 BOARD OUTLINE" at 11262.57,2881.73 h60
  text "5. LAYER TO LAYER REGISTRATION SHALL BE WITHIN +/-2 MIL." at 3666,2770.46 h60
  text "N.C. ROUTE" at 11262.57,2745.76 h60
  text "V. SCORE" at 12128.57,2745.76 h60
  text "X" at 11945.57,2739.82 h60
  text "6. REFER IMPEDANCE TABLE FOR IMPEDANCE CONTROL TRACES ON LAYER 1 & 4." at 3657.02,2649.6 h60
  text "CERTIFICATION:" at 10201.57,2616.64 h60
  text "MATERIALS AND WORKMANSHIP FOR ALL PCBS" at 10926.57,2616.64 h60
  text "TO MEET OR EXCEED THE REQUIREMENTS OF:" at 10926.57,2522.57 h60
  text "7. ALL VIAS ARE TENTED ON BOTH SIDES UNLESS OTHERWISE SOLDER MASK OPENED IN GERBER." at 3648.41,2488.15 h60
  text "X" at 10564.08,2393.95 h60
  text "ANSI IPC-A-600F CLASS ->" at 10692.07,2393.95 h60
  text "X" at 12340.08,2393.95 h60
  text "2" at 12450.07,2393.95 h60
  text "1" at 12135.07,2392.45 h60
  text "3" at 12804.07,2392.45 h60
  text "8. VIA HOLE OFFSET SHALL BE WITHIN 1MILS OF ITS ORIGINAL LOCATION" at 3652.35,2372.55 h60
  text "X" at 11376.08,2246.26 h60
  text "RoHS" at 11504.07,2246.26 h60
  text "OTHER" at 12148.48,2246.26 h60
  text "PER ORDER" at 12545.53,2246.26 h60
  text "ALL BOARDS MUST MEET OR EXCEED UL94-V0 REQUIREMENTS." at 10229.11,2092.43 h60
  text "C" at -1548.39,2091.37 h70
  text "C" at 13251.61,2091.37 h70
  text "PCB MUST BEAR THE UL94V-0 UL REGISTERED MATERIAL ID NUMBER" at 10229.11,1976.37 h60
  text "ADDITIONAL REQUIREMENTS:" at 10201.57,1806.94 h60
  text "MICROSECTION:" at 10276.34,1699.82 h60
  text "YES" at 11182.07,1699.82 h60
  text "REQUIRED" at 12043.57,1555.49 h60
  text "BARE BOARD ELEC. TEST:" at 10276.34,1552.63 h60
  text "NONE" at 11582.07,1552.63 h60
  text "X" at 11925.58,1552.63 h60
  text "PER ORDER" at 12635.57,1552.63 h60
  text "XX MIL VIAS REQUIRE NON-CONDUCTIVE FILL AND PLANARIZE" at 10460.11,1406.87 h59
  text "XX MIL VIAS REQUIRE CONDUCTIVE FILL AND PLANARIZE" at 10451.11,1247.87 h60
  text "OUTER XX MIL TRACES REQUIRE 50 OHM SINGLE-ENDED IMPEDANCE" at 10446.26,1104.97 h58
  text "LAYER 1 & 6 (INNER LAYERS) XX MIL WIDE, XX MIL SPACE / TRACES REQUIRE 100 OHM DIFFERENTIAL IMPEDANCE" at 10485.11,854.87 h60
  text "PROJECT TITLE:" at 10211.61,230.37 h45
  text ".PRJ_Title" at 10261.61,97.04 h70
  text "DESIGNED FOR:" at 10211.61,-70.63 h45
  text ".PRJ_Customer" at 10261.61,-210.63 h70
  text "D" at -1548.39,-278.63 h70
  text "D" at 13251.61,-278.63 h70
  text "FILE NAME:" at 10211.61,-370.63 h45
  text ".PCB_File_Name_No_Path" at 10261.61,-490.63 h70
  text "Texas Instruments (TI) and/or its licensors do not warrant the accuracy or completeness of this specification" at 5242.11,-652.47 h45
  text "ENGINEER:" at 10211.61,-660.63 h45
  text "LAYOUT BY:" at 11716.61,-660.63 h45
  text "or any information contained therein. TI and/or its licensors do not warrant that this design will meet" at 5197.13,-765.14 h45
  text ".PRJ_Engineer" at 10261.61,-815.63 h70
  text ".PCB_Layout" at 11767.11,-815.63 h70
  text "the specifications, will be suitable for your application or fit for any particular purpose, or will operate in" at 5197.13,-877.8 h45
  text ".Layer_Name" at -557.48,-906.25 h60
  text "ALTIUM DESIGNER VERSION:" at 11716.61,-970.63 h45
  text "an implementation. TI and/or its licensors do not warrant that the design is production worthy. You should" at 5197.13,-990.47 h45
  text "completely validate and test your design implementation to confirm the system functionality for your application." at 5242.11,-1103.13 h45
  text ".print_Scale" at 10261.61,-1103.96 h70
  text ".Application_BuildNumber" at 11767.11,-1103.96 h70
  text "1" at -392.05,-1310.63 h70
  text "2" at 2103.61,-1310.63 h70
  text "3" at 4592.95,-1310.63 h70
  text "4" at 7099.62,-1310.63 h70
  text "5" at 9598.61,-1310.63 h70
  text "6" at 11952.8,-1320.99 h70
M11 Gerber Information:
  lines w10: -1423.89,-977.3 5176.11,-977.3 ; -1423.89,-773.97 5178.11,-773.97 ; -1423.89,-570.63 -1423.89,-1180.63 2581.11,-1180.63 5178.11,-1180.63 5178.11,-570.63 -1423.39,-570.63 -1423.39,-1180.63 152.11,-1180.63 ; 1041.11,-1180.63 1041.11,-570.63 ; 2308.11,-773.97 2308.11,-570.63 ; 3148.11,-773.97 3148.11,-570.63 ; 3770.11,-1187.13 3770.11,-984.3
  text "ALL ARTWORK VIEWED FROM TOP SIDE" at -1360.39,-702.8 h60
  text "BOARD #:" at 1116.11,-702.8 h60
  text ".PRJ_Number" at 1661.61,-702.8 h60
  text "REV:" at 2506.11,-702.8 h60
  text ".PCB_Rev" at 2797.61,-702.8 h60
  text "SVN REV:" at 3344.11,-702.8 h60
  text ".VersionControl_RevNumber" at 3850.11,-702.8 h60
  text "LAYER NAME =" at -1360.39,-905.63 h60
  text "TID #:" at 1116.11,-906.13 h60
  text ".TID" at 1661.61,-906.13 h60
  text "PLOT NAME =" at -1360.39,-1111.47 h60
  text ".plot_File_Name" at -554.89,-1111.47 h60
  text "GENERATED    :" at 1118.11,-1111.47 h60
  text ".Print_Date" at 1987.61,-1111.47 h60
  text ".Print_Time" at 2716.61,-1111.47 h60
  text "TEXAS INSTRUMENTS" at 3981.11,-1111.47 h60
M12 Stackup:
  drawing of 396 lines, arcs and shapes, not listed
  text "NOTE :" at 6949.05,7550.24 h60
  text "1. THIS IS AN IMPEDANCE CONTROLLED BOARD." at 7117.6,7419.39 h60
  text "2. EXTERNAL LAYER CU THICKNESSES ARE FINISHED THICKNESS AFTER PLATING." at 7117.6,7321.51 h60
  text "6" at 9001.73,7158.82 h60
  text "IMPEDANCE TABLE :" at 7845.34,7143.44 h80
  text "LAYER" at 7164.62,6959.44 h70
  text "TRACE WIDTH" at 7451.82,6958.6 h70
  text "SPACING" at 7936.82,6958.6 h70
  text "IMPEDANCE +/- 10%" at 8271.82,6958.6 h70
  text "REFERENCE LAYER" at 8996.82,6958.6 h70
  text "4.5 MILS" at 7557.82,6786.26 h65
  text "LAYER-2" at 9136.36,6782.55 h65
  text "4.5 MILS" at 7958.73,6778.52 h65
  text "90 OHM" at 8431.85,6777.47 h65
  text "TOP" at 7138.15,6763.91 h70
  text "4.5 MILS" at 7552.78,6607.6 h65
  text "LAYER-3" at 9144.78,6606.24 h65
  text "4.5 MILS" at 7969.71,6600.7 h65
  text "BOTTOM" at 7147.26,6587.52 h60
  text "90 OHM" at 8440.2,6579.51 h65
  text "TOP /" at 7163.22,6451.87 h70
  text "LAYER-2" at 8985.5,6420.9 h65
  text "/ LAYER-3" at 9250.57,6418.69 h65
  text "-" at 8053.77,6416.28 h65
  text "50 OHM" at 8443.23,6412.03 h65
  text "5.9 MILS" at 7553.43,6408.53 h65
  text "BOTTOM" at 7119.33,6384.46 h60
  text "TOP" at 7183.8,6234.77 h70
  text "LAYER-2" at 9144.78,6228.54 h65
  text "4 MILS" at 7543.6,6224.76 h65
  text "6 MILS" at 7976.86,6223.08 h65
  text "100 OHM" at 8421.42,6219.2 h65
  text "LAYER-3" at 9136.34,6062.19 h65
  text "100 OHM" at 8430.2,6054.49 h65
  text "4 MILS" at 7552.32,6051.2 h65
  text "6 MILS" at 7985.58,6049.52 h65
  text "BOTTOM" at 7139.53,6033.35 h60
  text "LAYER STACK-UP :" at 3900.21,1925.77 h80
  text "Layer" at 3849.37,1774.02 h60
  text "Name" at 4259.28,1774.02 h60
  text "Material" at 5189.02,1774.02 h60
  text "Thickness" at 7168.43,1774.02 h60
  text "Constant" at 7818.26,1774.02 h60
  text "Board Layer Stack" at 8388.12,1774.02 h60
  text "Top Overlay" at 4259.28,1654.02 h60
  text "Top Solder" at 4259.28,1534.02 h60
  text "1.00mil" at 7168.43,1534.02 h60
  text "3.5" at 7818.26,1534.02 h60
  text "1" at 3849.37,1414.02 h60
  text "Top Layer" at 4259.28,1414.02 h60
  text "Copper Foil 12 microns" at 5189.02,1414.02 h60
  text "1.85mil" at 7168.43,1414.02 h60
  text "Dielectric 1" at 4259.28,1294.02 h60
  text "Iteq IT180A Prepreg 106 RC71-NEW" at 5189.02,1294.02 h60
  text "1.78mil" at 7168.43,1294.02 h60
  text "3.79" at 7818.26,1294.02 h60
  text "Dielectric 2" at 4259.28,1174.02 h60
  text "Iteq IT180A Prepreg 106 RC71-NEW" at 5189.02,1174.02 h60
  text "1.78mil" at 7168.43,1174.02 h60
  text "3.79" at 7818.26,1174.02 h60
  text "2" at 3849.37,1054.02 h60
  text "Int1 (GND)" at 4259.28,1054.02 h60
  text "2.76mil" at 7168.43,1054.02 h60
  text "Dielectric 3" at 4259.28,934.02 h60
  text "Iteq IT180A 50 mil core 1/1" at 5189.02,934.02 h60
  text "47.24mil" at 7168.43,934.02 h60
  text "4.28" at 7818.26,934.02 h60
  text "3" at 3849.37,814.02 h60
  text "Int2 (PWR)" at 4259.28,814.02 h60
  text "2.76mil" at 7168.43,814.02 h60
  text "Dielectric 4" at 4259.28,694.02 h60
  text "Iteq IT180A Prepreg 106 RC71-NEW" at 5189.02,694.02 h60
  text "1.78mil" at 7168.43,694.02 h60
  text "3.79" at 7818.26,694.02 h60
  text "Dielectric 5" at 4259.28,574.02 h60
  text "Iteq IT180A Prepreg 106 RC71-NEW" at 5189.02,574.02 h60
  text "1.78mil" at 7168.43,574.02 h60
  text "3.79" at 7818.26,574.02 h60
  text "4" at 3849.37,454.02 h60
  text "Bottom Layer" at 4259.28,454.02 h60
  text "Copper Foil 12 microns" at 5189.02,454.02 h60
  text "1.85mil" at 7168.43,454.02 h60
  text "Bottom Solder" at 4259.28,334.02 h60
  text "1.00mil" at 7168.43,334.02 h60
  text "3.5" at 7818.26,334.02 h60
  text "Bottom Overlay" at 4259.28,214.02 h60
  text "Total board thickness:" at 3849.37,94.02 h60
  text "65.57mil" at 7168.43,94.02 h60
  text ".Layer_Name" at -554.89,-905.63 h60
M13 Component Bodies Top:
  text ".Layer_Name" at -304.89,-905.63 h60
M14 Component Bodies Bottom:
  text ".Layer_Name" at -304.89,-905.63 h60
M15 Courtyards Top:
  text ".Layer_Name" at -304.89,-905.63 h60
M16 Courtyards Bottom:
  text ".Layer_Name" at -304.89,-905.63 h60
Drill Drawing:
  drawing of 153 lines, arcs and shapes, not listed
  text "Symbol" at -1218.98,7105.79 h72
  text "Count" at -713.11,7105.79 h72
  text "Hole Size" at -113.27,7105.79 h72
  text "Plated" at 1006.41,7105.79 h72
  text "Hole Type" at 1512.28,7105.79 h72
  text "Hole Tolerance (+)" at 2246.08,7105.79 h72
  text "Hole Tolerance (-)" at 3579.69,7105.79 h72
  text "Hole Length" at 4913.3,7105.79 h72
  text "1" at -713.11,6955.79 h60
  text "39.37mil (1.000mm)" at -113.27,6955.79 h60
  text "PTH" at 1006.41,6955.79 h60
  text "Rectangle" at 1512.28,6955.79 h60
  text "3.94mil (0.100mm)" at 2246.08,6955.79 h60
  text "3.94mil (0.100mm)" at 3579.69,6955.79 h60
  text "137.79mil (3.500mm)" at 4913.3,6955.79 h60
  text "1" at -713.11,6805.79 h60
  text "40.00mil (1.016mm)" at -113.27,6805.79 h60
  text "PTH" at 1006.41,6805.79 h60
  text "Round" at 1512.28,6805.79 h60
  text "3.00mil (0.076mm)" at 2246.08,6805.79 h60
  text "3.00mil (0.076mm)" at 3579.69,6805.79 h60
  text "-" at 4913.3,6805.79 h60
  text "A" at -1248.07,6795.8 h66.67
  text "2" at -713.11,6655.79 h60
  text "23.62mil (0.600mm)" at -113.27,6655.79 h60
  text "NPTH" at 1006.41,6655.79 h60
  text "Round" at 1512.28,6655.79 h60
  text "3.00mil (0.076mm)" at 2246.08,6655.79 h60
  text "3.00mil (0.076mm)" at 3579.69,6655.79 h60
  text "-" at 4913.3,6655.79 h60
  text "2" at -713.11,6505.79 h60
  text "33.47mil (0.850mm)" at -113.27,6505.79 h60
  text "NPTH" at 1006.41,6505.79 h60
  text "Round" at 1512.28,6505.79 h60
  text "3.00mil (0.076mm)" at 2246.08,6505.79 h60
  text "3.00mil (0.076mm)" at 3579.69,6505.79 h60
  text "-" at 4913.3,6505.79 h60
  text "2" at -713.11,6355.79 h60
  text "39.37mil (1.000mm)" at -113.27,6355.79 h60
  text "PTH" at 1006.41,6355.79 h60
  text "Rectangle" at 1512.28,6355.79 h60
  text "3.94mil (0.100mm)" at 2246.08,6355.79 h60
  text "3.94mil (0.100mm)" at 3579.69,6355.79 h60
  text "118.11mil (3.000mm)" at 4913.3,6355.79 h60
  text "2" at -713.11,6205.79 h60
  text "40.16mil (1.020mm)" at -113.27,6205.79 h60
  text "NPTH" at 1006.41,6205.79 h60
  text "Round" at 1512.28,6205.79 h60
  text "2.00mil (0.051mm)" at 2246.08,6205.79 h60
  text "2.00mil (0.051mm)" at 3579.69,6205.79 h60
  text "-" at 4913.3,6205.79 h60
  text "3" at -713.11,6055.79 h60
  text "43.31mil (1.100mm)" at -113.27,6055.79 h60
  text "PTH" at 1006.41,6055.79 h60
  text "Round" at 1512.28,6055.79 h60
  text "3.00mil (0.076mm)" at 2246.08,6055.79 h60
  text "3.00mil (0.076mm)" at 3579.69,6055.79 h60
  text "-" at 4913.3,6055.79 h60
  text "4" at -713.11,5905.79 h60
  text "7.87mil (0.200mm)" at -113.27,5905.79 h60
  text "PTH" at 1006.41,5905.79 h60
  text "Round" at 1512.28,5905.79 h60
  text "3.00mil (0.076mm)" at 2246.08,5905.79 h60
  text "3.00mil (0.076mm)" at 3579.69,5905.79 h60
  text "-" at 4913.3,5905.79 h60
  text "4" at -713.11,5755.79 h60
  text "23.62mil (0.600mm)" at -113.27,5755.79 h60
  text "PTH" at 1006.41,5755.79 h60
  text "Slot" at 1512.28,5755.79 h60
  text "3.00mil (0.076mm)" at 2246.08,5755.79 h60
  text "3.00mil (0.076mm)" at 3579.69,5755.79 h60
  text "51.18mil (1.300mm)" at 4913.3,5755.79 h60
  text "4" at -713.11,5605.79 h60
  text "33.47mil (0.850mm)" at -113.27,5605.79 h60
  text "PTH" at 1006.41,5605.79 h60
  text "Round" at 1512.28,5605.79 h60
  text "3.00mil (0.076mm)" at 2246.08,5605.79 h60
  text "3.00mil (0.076mm)" at 3579.69,5605.79 h60
  text "-" at 4913.3,5605.79 h60
  text "4" at -713.11,5455.79 h60
  text "118.11mil (3.000mm)" at -113.27,5455.79 h60
  text "PTH" at 1006.41,5455.79 h60
  text "Round" at 1512.28,5455.79 h60
  text "3.00mil (0.076mm)" at 2246.08,5455.79 h60
  text "3.00mil (0.076mm)" at 3579.69,5455.79 h60
  text "-" at 4913.3,5455.79 h60
  text "7" at -713.11,5305.79 h60
  text "23.62mil (0.600mm)" at -113.27,5305.79 h60
  text "PTH" at 1006.41,5305.79 h60
  text "Round" at 1512.28,5305.79 h60
  text "3.00mil (0.076mm)" at 2246.08,5305.79 h60
  text "3.00mil (0.076mm)" at 3579.69,5305.79 h60
  text "-" at 4913.3,5305.79 h60
  text "7" at -713.11,5155.79 h60
  text "40.16mil (1.020mm)" at -113.27,5155.79 h60
  text "PTH" at 1006.41,5155.79 h60
  text "Round" at 1512.28,5155.79 h60
  text "3.00mil (0.076mm)" at 2246.08,5155.79 h60
  text "3.00mil (0.076mm)" at 3579.69,5155.79 h60
  text "-" at 4913.3,5155.79 h60
  text "B" at -1248.07,5145.8 h66.67
  text "12" at -713.11,5005.79 h60
  text "22.05mil (0.560mm)" at -113.27,5005.79 h60
  text "NPTH" at 1006.41,5005.79 h60
  text "Round" at 1512.28,5005.79 h60
  text "3.00mil (0.076mm)" at 2246.08,5005.79 h60
  text "3.00mil (0.076mm)" at 3579.69,5005.79 h60
  text "-" at 4913.3,5005.79 h60
  text "603" at -713.11,4855.79 h60
  text "8.00mil (0.203mm)" at -113.27,4855.79 h60
  text "PTH" at 1006.41,4855.79 h60
  text "Round" at 1512.28,4855.79 h60
  text "3.00mil (0.076mm)" at 2246.08,4855.79 h60
  text "3.00mil (0.076mm)" at 3579.69,4855.79 h60
  text "-" at 4913.3,4855.79 h60
  text "658 Total" at -713.11,4705.79 h60
  text "Slot definitions :" at -1218.98,4560.81 h60
  text "Routed Path Length" at -186.3,4560.81 h60
  text "= Calculated from tool start centre position to tool end centre position." at 916.37,4560.81 h60
  text "Hole Length" at -186.3,4460.84 h60
  text "= Routed Path Length + Tool Size = Slot length as defined in the PCB layout" at 506.5,4460.84 h60
  text ".Layer_Name" at -554.89,-905.63 h60
M17 Embedded Cavity:
  text ".Layer_Name" at -554.89,-905.63 h60
M18 Embedded Assembly:
  text ".Layer_Name" at -554.89,-905.63 h60
M19 Embedded Keepout:
  text ".Layer_Name" at -554.89,-905.63 h60
DCA1000:
  drawing of 11001 lines, arcs and shapes, not listed
DXF_PANEL:
  drawing of 4593 lines, arcs and shapes, not listed

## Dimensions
-1102.34,1013.78 to 0.02,1013.78 on M2 Board Dimensions
-1102.34,1013.78 to -1102.34,541.26 on M2 Board Dimensions
0.02,541.26 to 0,0 on M2 Board Dimensions
0.02,1013.78 to 0,1555.12 on M2 Board Dimensions
0,1555.12 to 3149.61,1555.12 on M2 Board Dimensions
3149.61,1555.12 to 3149.61,0 on M2 Board Dimensions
